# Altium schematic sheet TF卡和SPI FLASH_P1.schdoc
size 297 x 209 mm; Symbol: Drawing-Symbol_A4; Company: 嘉立创EDA; Version: V1.0; Page Size: A4; @Project Name: 水墨屏demo1; @Page Count: 1; @Update Date: 2026-02-28; @Create Date: 2026-02-28; @Schematic Name: Schematic1; @Page No: 1; @Page Name: P1; Device: Drawing-Symbol_A4; @Board Name: Board1; @Create Time: 16:01:11; @Update Time: 16:01:11; @Assembly Variant: Basic; Border: 1; Title Block Position: 3; Size: A4; Width: 1170; Height: 825; Region Start: 1; X Region Count: 6; Y Region Count: 4; Blade Width: 10
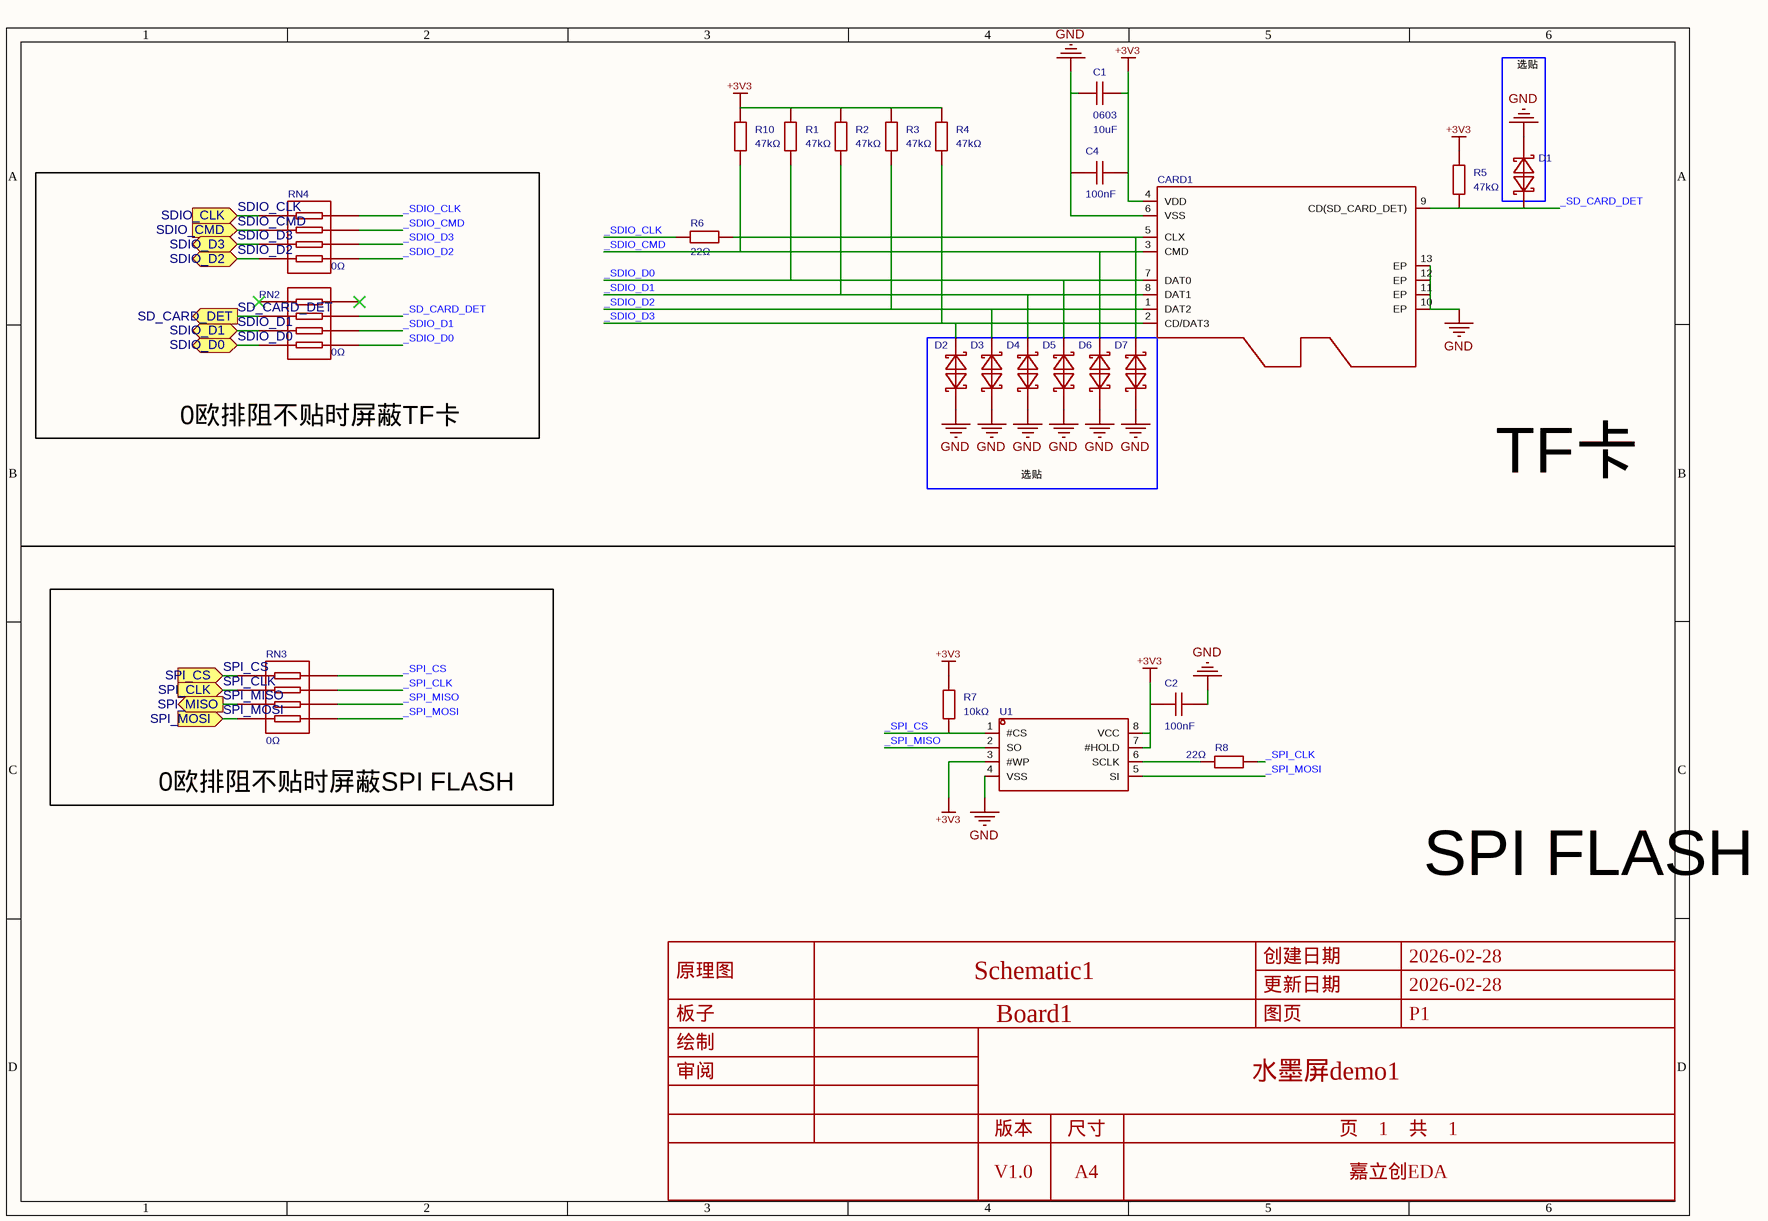
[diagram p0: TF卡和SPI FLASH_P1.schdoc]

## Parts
C1  Supplier Footprint: 0603  [C0603]  (hidden comment: 10uF)
C2  100nF  [C0603]
C4  100nF  [C0603]
CARD1  XKTF-015-G  [TF-SMD_XKTF-015-N]  (value not drawn)
D1  LESD8D5.0CAT5G  [DFN-2L_L1.0-W0.6-P0.65-BI]  (value not drawn)
D2  LESD8D5.0CAT5G  [DFN-2L_L1.0-W0.6-P0.65-BI]  (value not drawn)
D3  LESD8D5.0CAT5G  [DFN-2L_L1.0-W0.6-P0.65-BI]  (value not drawn)
D4  LESD8D5.0CAT5G  [DFN-2L_L1.0-W0.6-P0.65-BI]  (value not drawn)
D5  LESD8D5.0CAT5G  [DFN-2L_L1.0-W0.6-P0.65-BI]  (value not drawn)
D6  LESD8D5.0CAT5G  [DFN-2L_L1.0-W0.6-P0.65-BI]  (value not drawn)
D7  LESD8D5.0CAT5G  [DFN-2L_L1.0-W0.6-P0.65-BI]  (value not drawn)
R1  47kΩ  [R0603]
R2  47kΩ  [R0603]
R3  47kΩ  [R0603]
R4  47kΩ  [R0603]
R5  47kΩ  [R0603]
R6  22Ω  [R0603]
R7  10kΩ  [R0603]
R8  22Ω  [R0603]
R10  47kΩ  [R0603]
RN2  0Ω  [RES-ARRAY-SMD_0402-8P-L2.0-W1.0-BL]
RN3  0Ω  [RES-ARRAY-SMD_0402-8P-L2.0-W1.0-BL]
RN4  0Ω  [RES-ARRAY-SMD_0402-8P-L2.0-W1.0-BL]
U1  GD25Q32CSIGR  [SOIC-8_L5.3-W5.3-P1.27-LS8.0-BL]  (value not drawn)

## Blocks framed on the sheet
选贴: D1
0欧排阻不贴时屏蔽TF卡: RN2 RN4
选贴: D2-D7
0欧排阻不贴时屏蔽SPI FLASH: RN3

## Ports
SD_CARD_DET (out), SDIO_CLK (in), SDIO_CMD (in), SDIO_D0 (bidir), SDIO_D1 (bidir), SDIO_D2 (bidir), SDIO_D3 (bidir), SPI_CLK (in), SPI_CS (in), SPI_MISO (out), SPI_MOSI (in)

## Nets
+3V3: C1.1 C2.1 C4.2 CARD1.4(VDD) R1.2 R2.2 R3.2 R4.2 R5.2 R7.2 R10.2 U1.3(#WP) U1.7(#HOLD) U1.8(VCC)
GND: C1.2 C2.2 C4.1 CARD1.6(VSS) CARD1.10(EP) CARD1.11(EP) CARD1.12(EP) CARD1.13(EP) D1.2(K) D2.2(K) D3.2(K) D4.2(K) D5.2(K) D6.2(K) D7.2(K) U1.4(VSS)
_SD_CARD_DET: CARD1.9(CD(SD_CARD_DET)) D1.1(A) R5.1 RN2.3
_SDIO_CLK: R6.1 RN4.4
_SDIO_CMD: CARD1.3(CMD) D6.1(A) R10.1 RN4.3
_SDIO_D0: CARD1.7(DAT0) D5.1(A) R1.1 RN2.1
_SDIO_D1: CARD1.8(DAT1) D4.1(A) R2.1 RN2.2
_SDIO_D2: CARD1.1(DAT2) D3.1(A) R3.1 RN4.1
_SDIO_D3: CARD1.2(CD/DAT3) D2.1(A) R4.1 RN4.2
_SPI_CLK: R8.2 RN3.3
_SPI_CS: R7.1 RN3.4 U1.1(#CS)
_SPI_MISO: RN3.2 U1.2(SO)
_SPI_MOSI: RN3.1 U1.5(SI)
SD_CARD_DET: RN2.6 ; port SD_CARD_DET
SDIO_CLK: RN4.5 ; port SDIO_CLK
SDIO_CMD: RN4.6 ; port SDIO_CMD
SDIO_D0: RN2.8 ; port SDIO_D0
SDIO_D1: RN2.7 ; port SDIO_D1
SDIO_D2: RN4.8 ; port SDIO_D2
SDIO_D3: RN4.7 ; port SDIO_D3
SPI_CLK: RN3.6 ; port SPI_CLK
SPI_CS: RN3.5 ; port SPI_CS
SPI_MISO: RN3.7 ; port SPI_MISO
SPI_MOSI: RN3.8 ; port SPI_MOSI
NetCARD1_5: CARD1.5(CLX) D7.1(A) R6.2
NetR8_1: R8.1 U1.6(SCLK)

Not connected (* = marked no-connect by the designer): RN2 4* 5*

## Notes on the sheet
- TF卡
- SPI FLASH

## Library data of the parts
C1 = 0603X106K100NT: 容值:10uF;精度:±10%;额定电压:10V;材质(温度系数):X5R;; Manufacturer: FH(风华); 3D Model: ac125912035d415993ca9572d50418b1; 3D Model Transform: 62.992,31.496,0,0,0,0,0,0,0; Tolerance: ±10%; Voltage Rated: 10V; Temperature Coefficient: X5R; AddInBom: yes; ModelName: C0603_L1.6-W0.8-H0.8
C2 C4 = CGA0603X7R104K500JT: 容值:100nF;精度:±10%;额定电压:50V;温度系数:X7R;; Manufacturer: HRE(芯声); 3D Model: ac125912035d415993ca9572d50418b1; 3D Model Transform: 62.992,31.496,0,0,0,0,0,0,0; Tolerance: ±10%; Voltage Rating: 50V; Temperature Coefficient: X7R; AddInBom: yes; ModelName: C0603_L1.6-W0.8-H0.8
CARD1 = XKTF-015-G（自修改）: 卡连接方式:自弹式;卡类型:MicroSD卡(TF卡);连接器类型:卡座;本体最大高度:2mm;触头材质:铜合金;触头镀层:金;工作温度范围:-25℃~+90℃;焊接温度(最大值):260℃;; Manufacturer: XKB Connectivity(中国星坤); Card Connection Mode: 自弹式; Connector Type: 卡座; Maximum Body Height: 2mm; Welding Temperature (Max): 260℃; 3D Model: 2461a61de4d247f088502c0efe92caf1; 3D Model Transform: 635.826,598.424,0,0,0,0,0,-81.969,-23.622; AddInBom: yes
D1-D7 = LESD8D5.0CAT5G_C2987694: Manufacturer: UMW(友台半导体); 3D Model: 7b44c43a15a54fb6b2a4afad776bd37d; 3D Model Transform: 40.1574,24.4094,0,0,0,0,0,0,0; AddInBom: yes; ModelName: DFN-2L_L1.0-W0.6-0.5-P0.65-BI
R1-R5 R10 = 0603WAF4702T5E: 电阻类型:厚膜电阻;阻值:47kΩ;精度:±1%;功率:100mW;工作电压:75V;温度系数:±100ppm/℃;; Manufacturer: UNI-ROYAL(厚声); AddInBom: yes; ModelId: fc143cca1e79419f9cd78b61e9279f080819f05c4eef4c71ace90d822a990e87; ModelTransform: 31.8897,63.7794,0,90,0,0,0,0,0; Tolerance: ±1%; Power(Watts): 100mW; Voltage-Supply(Max): 75V
R6 R8 = RC0603JR-0722RL: 电阻类型:厚膜电阻;阻值:22Ω;精度:±5%;功率:100mW;最大工作电压:75V;温度系数:±100ppm/℃;; Manufacturer: YAGEO(国巨); AddInBom: yes; ModelId: fc143cca1e79419f9cd78b61e9279f080819f05c4eef4c71ace90d822a990e87; ModelTransform: 31.8897,63.7794,0,90,0,0,0,0,0; Tolerance: ±5%; Power(Watts): 100mW; Overload Voltage (Max): 75V
R7 = RC0603FR-0710KL: 电阻类型:厚膜电阻;阻值:10kΩ;精度:±1%;功率:100mW;最大工作电压:75V;温度系数:±100ppm/℃;; Manufacturer: YAGEO(国巨); 3D Model: fc143cca1e79419f9cd78b61e9279f080819f05c4eef4c71ace90d822a990e87; 3D Model Transform: 31.8897,63.7794,0,90,0,0,0,0,0; Tolerance: ±1%; Power(Watts): 100mW; Overload Voltage (Max): 75V; AddInBom: yes
RN2-RN4 = YC124-JR-070RL: 阻值:0Ω;单个元件功率:62.5mW;电阻器数:4;; Manufacturer: YAGEO(国巨); 3D Model: 24809bea39114057b1cb601d1f696a88; 3D Model Transform: 78.74,39.37,0,180,0,0,-0.001,-0.001,0; Power(Watts): 62.5mW; Number of Resistors: 4; Temperature Coefficient: ±250ppm/℃; AddInBom: yes; ModelName: R0402-8P_L2.0-W1.0-H0.5
U1 = GD25Q32CSIGR: Manufacturer: GigaDevice(兆易创新); Symbol: GD25Q32CSIG_C318845; 不贴标志: X; 3D Model: f83d990ad74f400caf5ac920b7771508; 3D Model Transform: 208.661,311.25654,0,0,0,0,-0.0005,0.0005,0; AddInBom: yes; ModelName: SOIC-8_L5.3-W5.3-H1.9-LS7.9-P1.27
